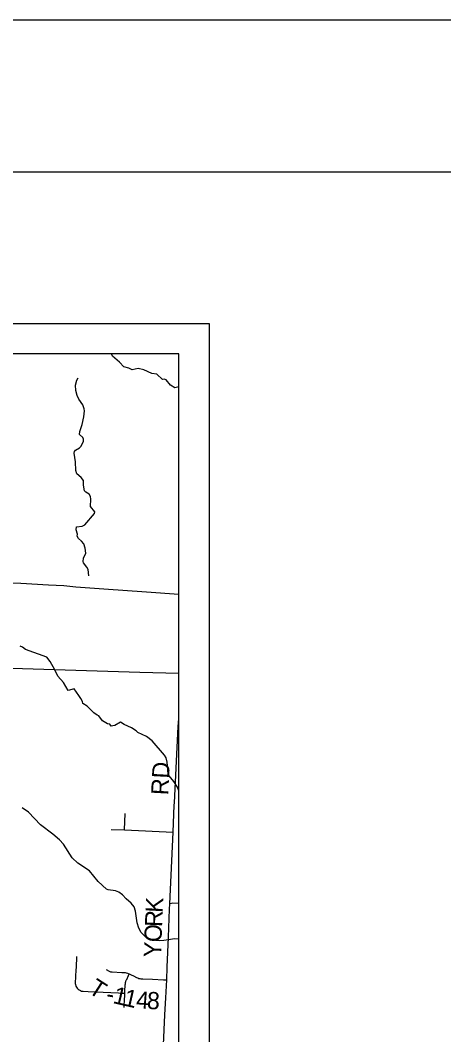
# Model space of a CAD drawing. Extents: x 0 to 34, y 0 to 22.
# Drawn here: x 8.377 to 9.774, y 18.654 to 22 of the extents above; entities that cross this region are included whole.
import ezdxf

# ---------------------------------------------------------------- set-up
doc = ezdxf.new("R2010")
doc.units = 0
for name, color, linetype in [('GM_X_Corporation', 7, 'Continuous'), ('GM_X_County_Road', 7, 'Continuous'), ('GM_X_County_Road_Text', 7, 'Continuous'), ('GM_X_Minor_River', 7, 'Continuous'), ('GM_X_Rail_Line', 7, 'Continuous'), ('GM_X_Township_Road', 7, 'Continuous'), ('GM_X_Township_Road_Text', 7, 'Continuous'), ('SH_Border', 7, 'Continuous'), ('SH_Cut_Line', 7, 'Continuous'), ('SH_Data', 7, 'Continuous')]:
    doc.layers.add(name, color=color, linetype=linetype)

msp = doc.modelspace()

# ---------------------------------------------------------------- linework, layer by layer
at = {"layer": 'GM_X_Corporation'}
msp.add_lwpolyline([(8.9, 18.0808), (8.9, 20.9), (6.4385, 20.9), (6.4325, 20.8009), (6.4277, 20.7531), (6.4097, 20.4361), (6.4016, 20.3608), (6.4001, 20.2844), (6.3927, 20.2003), (6.389, 20.1539), (6.3883, 20.1254), (6.385, 20.0884), (6.3621, 19.6044), (6.3556, 19.5188), (6.3374, 19.2897), (6.3253, 19.1073), (6.2646, 18.2231), (6.7672, 18.2007), (7.0679, 18.1923), (7.755, 18.1483), (7.8208, 18.1434), (8.8282, 18.0842)], close=True, dxfattribs=at)
at = {"layer": 'GM_X_County_Road'}
for points in [[(8.9, 20.1061), (8.7941, 20.1136), (8.6525, 20.1239), (8.5609, 20.1302), (8.5205, 20.1341), (8.4703, 20.137), (8.379, 20.142), (8.3264, 20.1449), (8.2317, 20.1527), (8.1581, 20.1576), (8.0256, 20.167), (7.9941, 20.1693), (7.9108, 20.1755)], [(8.8284, 18.0837), (8.8279, 18.0888), (8.8276, 18.0991), (8.8284, 18.128), (8.83, 18.1784), (8.8337, 18.2584), (8.8374, 18.3394), (8.8384, 18.3704), (8.8422, 18.4542), (8.8449, 18.5222), (8.8477, 18.5822), (8.8498, 18.62), (8.8543, 18.719), (8.8574, 18.775), (8.8603, 18.8346), (8.8624, 18.8771), (8.8657, 18.976), (8.8694, 19.0681), (8.8705, 19.0855), (8.8812, 19.3221), (8.8852, 19.4112), (8.8858, 19.4182), (8.8984, 19.6699), (8.9, 19.6963)]]:
    msp.add_lwpolyline(points, dxfattribs=at)
at = {"layer": 'GM_X_Minor_River'}
for points in [[(8.9, 20.791), (8.8866, 20.7881), (8.873, 20.7965), (8.8583, 20.8144), (8.8519, 20.816), (8.847, 20.8148), (8.8274, 20.8328), (8.8118, 20.8352), (8.7846, 20.8467), (8.7657, 20.8514), (8.7467, 20.8473), (8.7357, 20.853), (8.7187, 20.8566), (8.7051, 20.8718), (8.6814, 20.8924), (8.6787, 20.9)], [(8.6034, 20.1676), (8.6008, 20.1881), (8.5971, 20.1961), (8.5858, 20.2098), (8.5847, 20.2148), (8.5859, 20.2257), (8.5932, 20.2424), (8.5917, 20.2583), (8.5869, 20.2731), (8.5794, 20.2823), (8.5692, 20.2907), (8.5654, 20.2983), (8.5655, 20.3047), (8.5617, 20.3188), (8.5626, 20.3286), (8.5819, 20.3315), (8.5903, 20.3357), (8.6216, 20.373), (8.6231, 20.3783), (8.6084, 20.3958), (8.6105, 20.4208), (8.6086, 20.4292), (8.6045, 20.4364), (8.5939, 20.4429), (8.589, 20.4483), (8.5857, 20.4665), (8.5854, 20.482), (8.5783, 20.4915), (8.5639, 20.5034), (8.5606, 20.5152), (8.5592, 20.5436), (8.5548, 20.5721), (8.5556, 20.5774), (8.5591, 20.5823), (8.5727, 20.5894), (8.5773, 20.5943), (8.5819, 20.6022), (8.5854, 20.6113), (8.5858, 20.6178), (8.5836, 20.6234), (8.573, 20.6337), (8.5742, 20.6436), (8.5819, 20.6663), (8.5873, 20.6917), (8.589, 20.7121), (8.5883, 20.7178), (8.5834, 20.7315), (8.5706, 20.7498), (8.565, 20.7623), (8.5605, 20.7786), (8.5595, 20.7965), (8.5641, 20.8127), (8.568, 20.8207)], [(8.9, 19.4586), (8.8958, 19.4702), (8.8841, 19.4888), (8.8683, 19.5074), (8.8656, 19.5124), (8.8645, 19.5272), (8.8619, 19.553), (8.8585, 19.5674), (8.8533, 19.5762), (8.8128, 19.6237), (8.7935, 19.6378), (8.7652, 19.6504), (8.7599, 19.6557), (8.7444, 19.6664), (8.7205, 19.6771), (8.7084, 19.6851), (8.6895, 19.6737), (8.6823, 19.6722), (8.6766, 19.6718), (8.6732, 19.6783), (8.6649, 19.6787), (8.6486, 19.6894), (8.6369, 19.7053), (8.6305, 19.708), (8.6199, 19.7156), (8.5976, 19.7377), (8.584, 19.7465), (8.5825, 19.7529), (8.5772, 19.7632), (8.57, 19.7723), (8.5553, 19.7947), (8.5356, 19.7891), (8.5201, 19.8153), (8.5016, 19.837), (8.491, 19.8571), (8.4763, 19.8852), (8.465, 19.8997), (8.3946, 19.9249), (8.3844, 19.9325), (8.3772, 19.9352)], [(8.9, 18.969), (8.8876, 18.9703), (8.8505, 18.964), (8.8365, 18.9629), (8.8236, 18.9644), (8.8028, 18.969), (8.793, 18.9747), (8.7759, 18.9911), (8.7688, 19.0051), (8.7624, 19.0226), (8.7579, 19.061), (8.7526, 19.0754), (8.7436, 19.0876), (8.7269, 19.1016), (8.7145, 19.1157), (8.702, 19.1241), (8.691, 19.1279), (8.6668, 19.1318), (8.6619, 19.134), (8.6347, 19.1595), (8.606, 19.1938), (8.5666, 19.2197), (8.5489, 19.2375), (8.5194, 19.2824), (8.507, 19.2965), (8.4846, 19.3155), (8.4442, 19.3459), (8.4041, 19.3878), (8.3833, 19.4019)]]:
    msp.add_lwpolyline(points, dxfattribs=at)
at = {"layer": 'GM_X_Rail_Line'}
msp.add_lwpolyline([(2.1, 20.0629), (2.3112, 20.0558), (2.9425, 20.0365), (3.7259, 20.0086), (4.1377, 19.997), (4.5514, 19.9851), (5.3933, 19.9589), (5.7629, 19.946), (6.3762, 19.9275), (7.0828, 19.9047), (7.6933, 19.8843), (7.9626, 19.8754), (8.7713, 19.8495), (8.9, 19.8461)], dxfattribs=at)
at = {"layer": 'GM_X_Township_Road'}
msp.add_line((8.7212, 19.3294), (8.7232, 19.3838), dxfattribs=at)
for points in [[(8.677, 19.3309), (8.7212, 19.3294), (8.8812, 19.3221)], [(8.9, 19.0866), (8.8801, 19.0877), (8.8762, 19.0868), (8.8705, 19.0855)], [(8.563, 18.9117), (8.5626, 18.9039), (8.5603, 18.861), (8.5599, 18.8519), (8.5595, 18.8417), (8.5587, 18.8282), (8.5586, 18.823), (8.5593, 18.8189), (8.5609, 18.8142), (8.5626, 18.8107), (8.5646, 18.8078), (8.5678, 18.8041), (8.5715, 18.8015), (8.5755, 18.7992), (8.5796, 18.7978), (8.5845, 18.797), (8.6013, 18.7962), (8.6511, 18.7938), (8.7013, 18.7915), (8.7147, 18.7905), (8.7223, 18.7905)], [(8.6602, 18.8693), (8.67, 18.8629), (8.6753, 18.8613), (8.6799, 18.8608), (8.7128, 18.8592), (8.7189, 18.8589), (8.723, 18.8586), (8.7271, 18.8579), (8.7305, 18.8568), (8.7365, 18.8541), (8.7436, 18.8509), (8.7507, 18.8476), (8.7612, 18.8426), (8.765, 18.841), (8.7681, 18.8397), (8.7715, 18.839), (8.7755, 18.8385), (8.7821, 18.8382), (8.8131, 18.8369), (8.8499, 18.8353), (8.8594, 18.8347), (8.8603, 18.8346)], [(8.72, 18.7433), (8.7205, 18.7505), (8.7213, 18.768), (8.722, 18.7843), (8.7223, 18.7905), (8.7226, 18.797), (8.7237, 18.8178), (8.7242, 18.8215), (8.7249, 18.8256), (8.726, 18.8298), (8.7271, 18.8332), (8.7286, 18.8364), (8.7341, 18.8487), (8.7365, 18.8541)]]:
    msp.add_lwpolyline(points, dxfattribs=at)
at = {"layer": 'SH_Border'}
msp.add_lwpolyline([(1.5, 21.5), (33.5, 21.5), (33.5, 0.5), (1.5, 0.5)], close=True, dxfattribs=at)
at = {"layer": 'SH_Cut_Line'}
for points in [[(0, 0), (34, 0), (34, 22), (0, 22)], [(8.9, 15.4827), (8.9, 20.9), (2.1, 20.9), (2.1, 15.9442), (2.2903, 15.9292), (2.5827, 15.9132), (2.6921, 15.9056), (2.7799, 15.8989), (2.8362, 15.8952), (3.3132, 15.8609), (3.9945, 15.8088), (4.2803, 15.787), (4.5905, 15.7634), (4.92, 15.7429), (5.0952, 15.7318), (5.9419, 15.6782), (6.1109, 15.6683), (6.4, 15.6498), (6.624, 15.6351), (6.838, 15.6206), (7.6503, 15.5653), (8.6741, 15.4976)]]:
    msp.add_lwpolyline(points, close=True, dxfattribs=at)
at = {"layer": 'SH_Data'}
for p, q in [((2, 21), (9, 21)), ((9, 21), (9, 14))]:
    msp.add_line(p, q, dxfattribs=at)

# ---------------------------------------------------------------- texts
at = {"layer": 'GM_X_County_Road_Text'}
for s, height, rotation, p in [('RD', 0.05682, 87.0388, (8.8654, 19.443)), ('K', 0.0568, 86.924, (8.8468, 19.0549)), ('R', 0.0568, 87.8254, (8.845, 19.0085)), ('O', 0.0568, 87.8467, (8.8431, 18.9585)), ('Y', 0.0568, 87.8503, (8.8413, 18.9085))]:
    msp.add_text(s, height=height, rotation=rotation, dxfattribs=at).set_placement(p)
at = {"layer": 'GM_X_Township_Road_Text'}
for s, rotation, p in [('T', 327.2823, (8.5986, 18.7942)), ('1', 346.8119, (8.68, 18.7586)), ('-', 350.8057, (8.658, 18.7622)), ('1', 347.2214, (8.7145, 18.7506)), ('4', 355.931, (8.7579, 18.7414)), ('8', 357.1373, (8.7941, 18.7389))]:
    msp.add_text(s, height=0.0568, rotation=rotation, dxfattribs=at).set_placement(p)

doc.saveas('drawing.dxf')
